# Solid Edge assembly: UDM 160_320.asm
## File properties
Title: Zylinder
Author: ahadarics
Template: iso assembly.asm
Last saved by: ahadarics
Revision: 52
Application: Solid Edge
Username: ahadarics
Dokumentum tartalom típus: 1
Document Number: UDM 160/320
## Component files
Profilrohr 160_320.par
Mutter.par
Kolbenstange 160_320.par
Kit_1.par
Zugstange 160_320.par
Kit_2.par
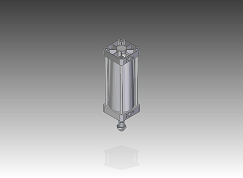
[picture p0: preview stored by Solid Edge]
